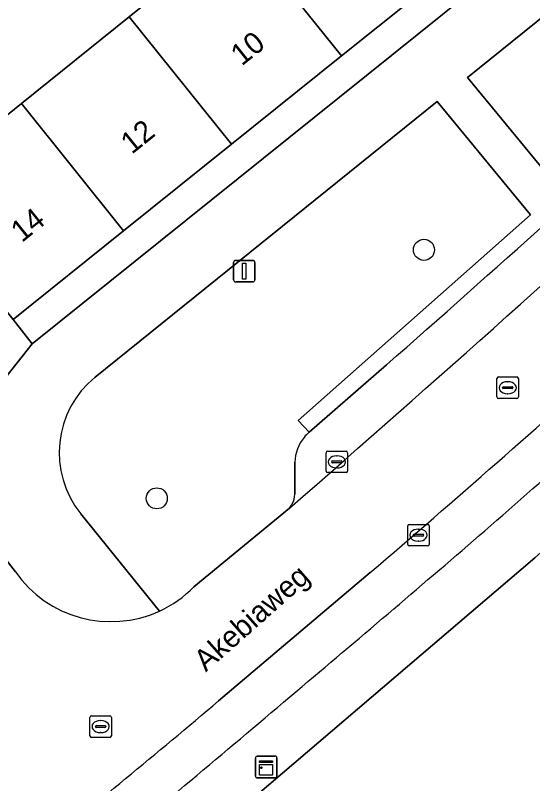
# Model space of a CAD drawing. Extents: x 162344 to 162869, y 381217 to 381818.
# Drawn here: x 162593.1 to 162617.14, y 381573.33 to 381609.01 of the extents above; entities that cross this region are included whole.
import ezdxf

# ---------------------------------------------------------------- set-up
doc = ezdxf.new("R2010")
doc.units = 0
for name, color, linetype in [('IMGEO_Boom', 7, 'Continuous'), ('IMGEO_Erf', 7, 'Continuous'), ('IMGEO_Groenvoorziening', 7, 'Continuous'), ('IMGEO_Kast', 7, 'Continuous'), ('IMGEO_Kolk', 7, 'Continuous'), ('IMGEO_Lichtmast', 7, 'Continuous'), ('IMGEO_Openbare_ruimte_label', 7, 'Continuous'), ('IMGEO_Pand', 7, 'Continuous'), ('IMGEO_Pand_nummerreeks', 7, 'Continuous'), ('IMGEO_Parkeervlak_open', 7, 'Continuous'), ('IMGEO_Rijbaan_lokaal_open', 7, 'Continuous'), ('IMGEO_Rioolput', 7, 'Continuous'), ('IMGEO_Voetpad_open', 7, 'Continuous')]:
    doc.layers.add(name, color=color, linetype=linetype)

msp = doc.modelspace()

# ---------------------------------------------------------------- linework, layer by layer
at = {"layer": 'IMGEO_Boom'}
for centre in [(162612.089, 381598.119), (162599.676, 381586.577)]:
    msp.add_circle(centre, 0.489, dxfattribs=at)
at = {"layer": 'IMGEO_Erf'}
msp.add_lwpolyline([(162624.28, 381630.339), (162618.835, 381635.59), (162615.058, 381631.44), (162615.96, 381630.598), (162612.904, 381627.212), (162609.777, 381630.035), (162606.262, 381627.745), (162607.37, 381626.124), (162603.382, 381623.399), (162599.633, 381620.838), (162598.316, 381622.766), (162588.949, 381616.664), (162591.647, 381613.341), (162588.696, 381610.944), (162585.998, 381614.267), (162585.08, 381613.516), (162586.977, 381611.168), (162582.48, 381607.587), (162588.265, 381600.781), (162593.384, 381604.909), (162598.393, 381608.947), (162603.495, 381613.061), (162608.464, 381617.068), (162613.728, 381621.312)], dxfattribs=at)
msp.add_lwpolyline([(162629.662, 381622.463), (162628.75, 381623.566), (162623.462, 381619.322), (162618.513, 381615.351), (162613.24, 381611.118), (162608.261, 381607.123), (162603.15, 381603.02), (162598.133, 381598.994), (162593.003, 381594.877), (162593.892, 381593.755)], close=True, dxfattribs=at)
at = {"layer": 'IMGEO_Groenvoorziening'}
for points in [[(162629.916, 381618.858), (162614.116, 381606.124), (162618.384, 381600.939), (162628.272, 381609.975), (162628.789, 381609.425), (162628.918, 381609.544)], [(162617.041, 381599.75), (162612.702, 381605.014), (162596.806, 381592.212)], [(162606.748, 381589.646), (162606.244, 381590.2), (162617.041, 381599.75)], [(162606.091, 381586.771), (162606.095, 381588.261)], [(162601.403, 381582.472), (162605.835, 381586.119)], [(162596.143, 381585.85), (162599.795, 381581.342)], [(162617.236, 381583.812), (162599.604, 381568.769), (162611.13, 381555.898), (162622.804, 381542.861), (162634.513, 381529.784), (162634.895, 381529.36)]]:
    msp.add_lwpolyline(points, dxfattribs=at)
for centre, radius, start, end in [((162599.701, 381588.695), 4.555, 129.4558, 218.6453), ((162607.879, 381588.314), 1.747, 130.3263, 141.1491), ((162607.956, 381588.228), 1.862, 140.5909, 178.9871), ((162605.031, 381586.812), 1.061, 332.3969, 357.8036), ((162605.025, 381586.813), 1.067, 319.3854, 332.4487), ((162597.556, 381586.238), 5.384, 294.5799, 315.6143)]:
    msp.add_arc(centre, radius, start, end, dxfattribs=at)
at = {"layer": 'IMGEO_Kast'}
for p, q in [((162604.257, 381573.675), (162604.257, 381574.516)), ((162604.257, 381574.516), (162604.257, 381573.675)), ((162604.332, 381574.6), (162605.173, 381574.6)), ((162605.173, 381574.6), (162604.332, 381574.6)), ((162605.257, 381574.525), (162605.257, 381573.684)), ((162605.257, 381573.684), (162605.257, 381574.525)), ((162605.182, 381573.6), (162604.341, 381573.6)), ((162604.341, 381573.6), (162605.182, 381573.6))]:
    msp.add_line(p, q, dxfattribs=at)
for points in [[(162604.452, 381574.39), (162605.052, 381574.39), (162605.052, 381574.305), (162604.452, 381574.305), (162604.452, 381574.39)], [(162604.452, 381574.215), (162605.052, 381574.215), (162605.052, 381573.726), (162604.452, 381573.726), (162604.452, 381574.215)]]:
    msp.add_lwpolyline(points, dxfattribs=at)
msp.add_circle((162604.536, 381574.064), 0.0377, dxfattribs=at)
for centre, start, end in [((162604.335, 381574.522), 92.4484, 184.2845), ((162604.335, 381574.522), 92.4484, 184.2845), ((162605.179, 381574.522), 2.4484, 94.2845), ((162605.179, 381574.522), 2.4484, 94.2845), ((162604.335, 381573.678), 182.4484, 274.2845), ((162604.335, 381573.678), 182.4484, 274.2845), ((162605.179, 381573.678), 272.4484, 4.2845), ((162605.179, 381573.678), 272.4484, 4.2845)]:
    msp.add_arc(centre, 0.0779, start, end, dxfattribs=at)
at = {"layer": 'IMGEO_Kolk'}
for p, q in [((162607.616, 381588.772), (162608.468, 381588.772)), ((162607.541, 381587.846), (162607.541, 381588.698)), ((162608.029, 381588.552), (162608.054, 381588.552)), ((162608.542, 381588.698), (162608.542, 381587.846)), ((162607.8, 381588.266), (162607.8, 381588.278)), ((162608.238, 381588.229), (162607.84, 381588.229)), ((162607.843, 381588.315), (162608.241, 381588.315)), ((162608.284, 381588.278), (162608.284, 381588.266)), ((162608.468, 381587.772), (162607.616, 381587.772)), ((162608.052, 381587.992), (162608.027, 381587.992)), ((162611.334, 381584.441), (162611.334, 381585.293)), ((162611.409, 381585.367), (162612.261, 381585.367)), ((162612.335, 381585.293), (162612.335, 381584.441)), ((162611.593, 381584.861), (162611.593, 381584.873)), ((162611.636, 381584.91), (162612.034, 381584.91)), ((162611.822, 381585.147), (162611.847, 381585.147)), ((162612.077, 381584.873), (162612.077, 381584.861)), ((162612.031, 381584.824), (162611.633, 381584.824)), ((162611.845, 381584.587), (162611.82, 381584.587)), ((162612.261, 381584.367), (162611.409, 381584.367))]:
    msp.add_line(p, q, dxfattribs=at)
for points in [[(162607.616, 381588.772), (162608.468, 381588.772)], [(162607.541, 381587.846), (162607.541, 381588.698)], [(162608.542, 381588.698), (162608.542, 381587.846)], [(162608.468, 381587.772), (162607.616, 381587.772)], [(162611.334, 381584.441), (162611.334, 381585.293)], [(162611.409, 381585.367), (162612.261, 381585.367)], [(162612.335, 381585.293), (162612.335, 381584.441)], [(162612.261, 381584.367), (162611.409, 381584.367)]]:
    msp.add_lwpolyline(points, dxfattribs=at)
for centre, radius, start, end in [((162607.618, 381588.696), 0.0765, 91.552, 178.448), ((162607.618, 381588.696), 0.0765, 91.552, 178.448), ((162608.466, 381588.696), 0.0765, 1.552, 88.448), ((162608.466, 381588.696), 0.0765, 1.552, 88.448), ((162607.84, 381588.275), 0.0403, 85.8775, 175.7526), ((162607.837, 381588.265), 0.0366, 178.938, 274.7102), ((162608.241, 381588.272), 0.043, 264.8664, 352.4533), ((162608.245, 381588.277), 0.0386, 1.7309, 96.639), ((162607.618, 381587.848), 0.0765, 181.552, 268.448), ((162607.618, 381587.848), 0.0765, 181.552, 268.448), ((162608.466, 381587.848), 0.0765, 271.552, 358.448), ((162608.466, 381587.848), 0.0765, 271.552, 358.448), ((162611.411, 381585.291), 0.0765, 91.552, 178.448), ((162611.411, 381585.291), 0.0765, 91.552, 178.448), ((162612.259, 381585.291), 0.0765, 1.552, 88.448), ((162612.259, 381585.291), 0.0765, 1.552, 88.448), ((162611.633, 381584.87), 0.0403, 85.8775, 175.7526), ((162611.63, 381584.86), 0.0366, 178.938, 274.7102), ((162612.034, 381584.867), 0.043, 264.8664, 352.4533), ((162612.038, 381584.872), 0.0386, 1.7309, 96.639), ((162611.411, 381584.443), 0.0765, 181.552, 268.448), ((162611.411, 381584.443), 0.0765, 181.552, 268.448), ((162612.259, 381584.443), 0.0765, 271.552, 358.448), ((162612.259, 381584.443), 0.0765, 271.552, 358.448)]:
    msp.add_arc(centre, radius, start, end, dxfattribs=at)
for centre, major_axis, ratio, start_param, end_param in [((162608.028, 381588.272), (-0.387, 0.002), 0.722429, 4.712389, 7.853982), ((162608.053, 381588.272), (-0.39, 0.002), 0.717154, 1.570796, 4.712389), ((162611.821, 381584.867), (-0.387, 0.002), 0.722429, 4.712389, 7.853982), ((162611.846, 381584.867), (-0.39, 0.002), 0.717154, 1.570796, 4.712389)]:
    msp.add_ellipse(centre, major_axis=major_axis, ratio=ratio, start_param=start_param, end_param=end_param, dxfattribs=at)
at = {"layer": 'IMGEO_Lichtmast'}
for p, q in [((162603.245, 381596.73), (162603.245, 381597.53)), ((162603.245, 381597.53), (162603.245, 381596.73)), ((162603.345, 381597.63), (162604.135, 381597.63)), ((162604.135, 381597.63), (162603.345, 381597.63)), ((162604.235, 381597.53), (162604.235, 381596.73)), ((162604.235, 381596.73), (162604.235, 381597.53)), ((162604.135, 381596.63), (162603.345, 381596.63)), ((162603.345, 381596.63), (162604.135, 381596.63))]:
    msp.add_line(p, q, dxfattribs=at)
msp.add_lwpolyline([(162603.665, 381597.505), (162603.815, 381597.505), (162603.815, 381596.755), (162603.665, 381596.755), (162603.665, 381597.505)], dxfattribs=at)
for centre, start, end in [((162603.345, 381597.53), 90, 180), ((162603.345, 381597.53), 90, 180), ((162604.135, 381597.53), 0, 90), ((162604.135, 381597.53), 360, 90), ((162603.345, 381596.73), 180, 270), ((162603.345, 381596.73), 180, 270), ((162604.135, 381596.73), 270, 0), ((162604.135, 381596.73), 270, 0)]:
    msp.add_arc(centre, 0.1, start, end, dxfattribs=at)
at = {"layer": 'IMGEO_Pand'}
for points in [[(162608.261, 381607.123), (162613.24, 381611.118), (162608.464, 381617.068), (162603.495, 381613.061)], [(162608.261, 381607.123), (162603.495, 381613.061), (162598.393, 381608.947), (162603.15, 381603.02)], [(162593.384, 381604.909), (162598.133, 381598.994), (162603.15, 381603.02), (162598.393, 381608.947)], [(162593.384, 381604.909), (162588.265, 381600.781), (162593.003, 381594.877), (162598.133, 381598.994)]]:
    msp.add_lwpolyline(points, close=True, dxfattribs=at)
at = {"layer": 'IMGEO_Parkeervlak_open'}
for points in [[(162610.351, 381592.776), (162606.748, 381589.646)], [(162606.095, 381588.261), (162606.091, 381586.771)], [(162609.593, 381583.132), (162602.55, 381577.172)]]:
    msp.add_lwpolyline(points, dxfattribs=at)
for centre, radius, start, end in [((162012.532, 382272.566), 905.263, 311.328974, 312.594769), ((161942.339, 382348.939), 1011, 311.016557, 312.544247), ((162205.379, 382055.51), 621.715, 310.553643, 311.98853), ((162286.159, 381962.013), 500.168, 311.09424, 312.45287), ((162607.879, 381588.314), 1.747, 130.3263, 141.1491), ((162607.956, 381588.228), 1.862, 140.5909, 178.9871), ((162605.031, 381586.812), 1.061, 332.3969, 357.8036), ((162605.025, 381586.813), 1.067, 319.3854, 332.4487), ((161962.733, 382342.089), 999.211, 310.105994, 310.745584), ((161624.099, 382738.088), 1520.247, 309.799914, 310.253015), ((162306.96, 381926.435), 457.557, 308.83123, 310.24208)]:
    msp.add_arc(centre, radius, start, end, dxfattribs=at)
at = {"layer": 'IMGEO_Rijbaan_lokaal_open'}
for points in [[(162593.104, 381583.166), (162592.337, 381584.135), (162588.977, 381588.297), (162588.864, 381588.438), (162577.813, 381602.191), (162577.762, 381602.246), (162574.68, 381606.059), (162574.574, 381606.188), (162573.231, 381607.826), (162555.033, 381630.367), (162552.464, 381628.263), (162557.077, 381622.564), (162568.008, 381609.06), (162573.172, 381602.64), (162576.33, 381598.754), (162579.594, 381594.706), (162585.923, 381586.92), (162590.428, 381581.301)], [(162605.835, 381586.119), (162601.403, 381582.472)], [(162602.55, 381577.172), (162609.593, 381583.132)]]:
    msp.add_lwpolyline(points, dxfattribs=at)
for centre, radius, start, end in [((161942.339, 382348.939), 1011, 311.016557, 312.544247), ((162205.379, 382055.51), 621.715, 310.553643, 311.98853), ((162597.542, 381586.26), 5.41, 214.8847, 294.6181), ((162597.556, 381586.238), 5.384, 294.5799, 315.6143), ((162306.96, 381926.435), 457.557, 308.83123, 310.24208)]:
    msp.add_arc(centre, radius, start, end, dxfattribs=at)
at = {"layer": 'IMGEO_Rioolput'}
for p, q in [((162615.479, 381591.288), (162615.479, 381592.14)), ((162615.554, 381592.214), (162616.406, 381592.214)), ((162615.967, 381591.994), (162615.992, 381591.994)), ((162616.48, 381592.14), (162616.48, 381591.288)), ((162615.738, 381591.708), (162615.738, 381591.72)), ((162616.176, 381591.671), (162615.778, 381591.671)), ((162615.781, 381591.757), (162616.179, 381591.757)), ((162616.222, 381591.72), (162616.222, 381591.708)), ((162615.99, 381591.434), (162615.965, 381591.434)), ((162616.406, 381591.214), (162615.554, 381591.214)), ((162596.566, 381575.551), (162596.566, 381576.403)), ((162596.641, 381576.477), (162597.493, 381576.477)), ((162597.567, 381576.403), (162597.567, 381575.551)), ((162596.825, 381575.971), (162596.825, 381575.983)), ((162597.263, 381575.934), (162596.865, 381575.934)), ((162596.868, 381576.02), (162597.266, 381576.02)), ((162597.054, 381576.257), (162597.079, 381576.257)), ((162597.309, 381575.983), (162597.309, 381575.971)), ((162597.077, 381575.697), (162597.052, 381575.697)), ((162597.493, 381575.477), (162596.641, 381575.477))]:
    msp.add_line(p, q, dxfattribs=at)
for points in [[(162615.479, 381591.288), (162615.479, 381592.14)], [(162615.554, 381592.214), (162616.406, 381592.214)], [(162616.48, 381592.14), (162616.48, 381591.288)], [(162616.406, 381591.214), (162615.554, 381591.214)], [(162596.566, 381575.551), (162596.566, 381576.403)], [(162596.641, 381576.477), (162597.493, 381576.477)], [(162597.567, 381576.403), (162597.567, 381575.551)], [(162597.493, 381575.477), (162596.641, 381575.477)]]:
    msp.add_lwpolyline(points, dxfattribs=at)
for centre, radius, start, end in [((162615.556, 381592.138), 0.0765, 91.552, 178.448), ((162615.556, 381592.138), 0.0765, 91.552, 178.448), ((162616.404, 381592.138), 0.0765, 1.552, 88.448), ((162616.404, 381592.138), 0.0765, 1.552, 88.448), ((162615.778, 381591.717), 0.0403, 85.8775, 175.7526), ((162615.775, 381591.707), 0.0366, 178.938, 274.7102), ((162616.179, 381591.714), 0.043, 264.8664, 352.4533), ((162616.183, 381591.719), 0.0386, 1.7309, 96.639), ((162615.556, 381591.29), 0.0765, 181.552, 268.448), ((162615.556, 381591.29), 0.0765, 181.552, 268.448), ((162616.404, 381591.29), 0.0765, 271.552, 358.448), ((162616.404, 381591.29), 0.0765, 271.552, 358.448), ((162596.643, 381576.401), 0.0765, 91.552, 178.448), ((162596.643, 381576.401), 0.0765, 91.552, 178.448), ((162597.491, 381576.401), 0.0765, 1.552, 88.448), ((162597.491, 381576.401), 0.0765, 1.552, 88.448), ((162596.865, 381575.98), 0.0403, 85.8775, 175.7526), ((162596.862, 381575.97), 0.0366, 178.938, 274.7102), ((162597.266, 381575.977), 0.043, 264.8664, 352.4533), ((162597.27, 381575.982), 0.0386, 1.7309, 96.639), ((162596.643, 381575.553), 0.0765, 181.552, 268.448), ((162596.643, 381575.553), 0.0765, 181.552, 268.448), ((162597.491, 381575.553), 0.0765, 271.552, 358.448), ((162597.491, 381575.553), 0.0765, 271.552, 358.448)]:
    msp.add_arc(centre, radius, start, end, dxfattribs=at)
for centre, major_axis, ratio, start_param, end_param in [((162615.966, 381591.714), (-0.387, 0.002), 0.722429, 4.712389, 7.853982), ((162615.991, 381591.714), (-0.39, 0.002), 0.717154, 1.570796, 4.712389), ((162597.053, 381575.977), (-0.387, 0.002), 0.722429, 4.712389, 7.853982), ((162597.078, 381575.977), (-0.39, 0.002), 0.717154, 1.570796, 4.712389)]:
    msp.add_ellipse(centre, major_axis=major_axis, ratio=ratio, start_param=start_param, end_param=end_param, dxfattribs=at)
at = {"layer": 'IMGEO_Voetpad_open'}
for points in [[(162588.284, 381559.145), (162591.596, 381561.939), (162592.32, 381562.545), (162599.456, 381568.935), (162599.604, 381568.769), (162617.236, 381583.812), (162622.507, 381588.51), (162623.179, 381589.147), (162630.312, 381595.808), (162647.237, 381612.021), (162652.285, 381616.955), (162652.976, 381617.664), (162659.686, 381624.575), (162660.865, 381625.672), (162663.359, 381627.992), (162668.299, 381632.588), (162675.845, 381641.49)], [(162636.787, 381622.23), (162636.238, 381622.763), (162635.145, 381623.708), (162633.2, 381625.535), (162629.662, 381622.463), (162593.892, 381593.755), (162592.435, 381591.907), (162592.334, 381590.062)], [(162625.222, 381606.148), (162628.789, 381609.425), (162628.272, 381609.975), (162618.384, 381600.939), (162614.116, 381606.124), (162629.916, 381618.858)], [(162592.435, 381591.907), (162593.892, 381593.755), (162593.003, 381594.877), (162588.265, 381600.781), (162582.48, 381607.587)], [(162596.806, 381592.212), (162612.702, 381605.014)], [(162612.702, 381605.014), (162617.041, 381599.75), (162606.244, 381590.2), (162606.748, 381589.646), (162610.351, 381592.776)], [(162588.864, 381588.438), (162588.977, 381588.297), (162592.337, 381584.135), (162593.104, 381583.166)], [(162599.795, 381581.342), (162596.143, 381585.85)]]:
    msp.add_lwpolyline(points, dxfattribs=at)
for centre, radius, start, end in [((162012.532, 382272.566), 905.263, 311.328974, 312.594769), ((162286.159, 381962.013), 500.168, 311.09424, 312.45287), ((162599.701, 381588.695), 4.555, 129.4558, 218.6453), ((161962.733, 382342.089), 999.211, 310.105994, 310.745584), ((162597.542, 381586.26), 5.41, 214.8847, 294.6181), ((161624.099, 382738.088), 1520.247, 309.799914, 310.253015)]:
    msp.add_arc(centre, radius, start, end, dxfattribs=at)

# ---------------------------------------------------------------- texts
at = {"layer": 'IMGEO_Openbare_ruimte_label'}
msp.add_text('Akebiaweg', height=1, rotation=41.5146, dxfattribs=at).set_placement((162601.955, 381578.486))
at = {"layer": 'IMGEO_Pand_nummerreeks'}
for s, p in [('10', (162603.622, 381606.63)), ('12', (162598.51, 381602.527)), ('14', (162593.405, 381598.431))]:
    msp.add_text(s, height=1, rotation=38.749, dxfattribs=at).set_placement(p)

doc.saveas('drawing.dxf')
